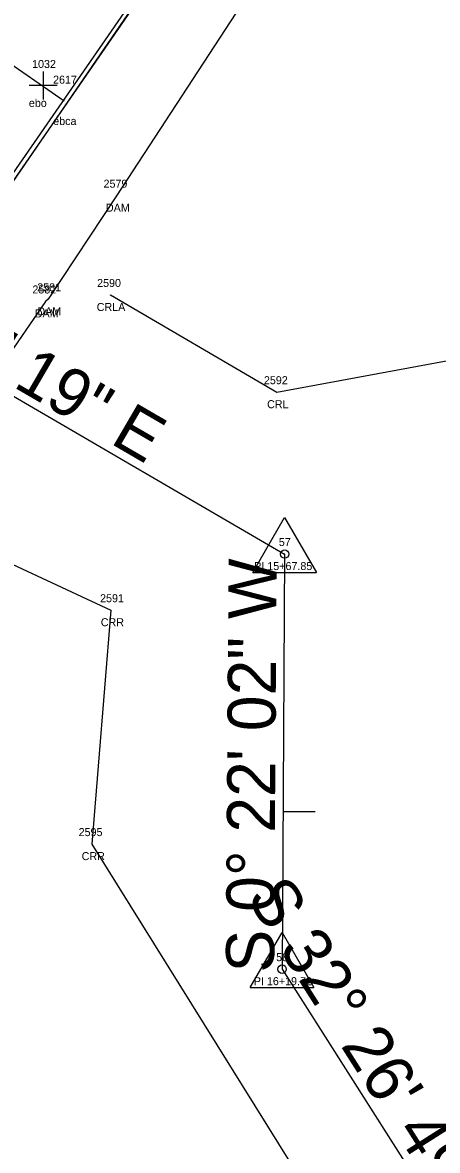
# Model space of a CAD drawing. Extents: x 2266664 to 2272542, y 716533 to 724777.
# Drawn here: x 2271122.9 to 2271174.6, y 722810 to 722951 of the extents above; entities that cross this region are included whole.
import ezdxf

# ---------------------------------------------------------------- set-up
doc = ezdxf.new("R2010")
doc.units = 0
for name, color, linetype in [('RD_EX_Bridge', 7, 'Continuous'), ('RD_EX_Dam', 7, 'Continuous'), ('RD_EX_Dam_txCode', 7, 'Continuous'), ('RD_EX_H2O', 7, 'Continuous'), ('RD_EX_H2O_txCode', 7, 'Continuous'), ('RD_EX_Misc', 7, 'Continuous'), ('RD_EX_Misc_txCode', 7, 'Continuous'), ('RD_HC_Cl', 7, 'Continuous'), ('RD_HC_Data', 7, 'Continuous'), ('RD_HC_Data_Tic', 7, 'Continuous'), ('RD_HC_txCode', 7, 'Continuous'), ('RD_SMD_Locator', 7, 'Continuous')]:
    doc.layers.add(name, color=color, linetype=linetype)

msp = doc.modelspace()

# ---------------------------------------------------------------- linework, layer by layer
at = {"layer": 'RD_EX_Bridge'}
msp.add_lwpolyline([(2271154.4, 722979.52), (2271126.52, 722998.67), (2271058.56, 722899.96), (2271086.24, 722880.86), (2271154.4, 722979.52)], dxfattribs=at)
at = {"layer": 'RD_EX_Dam'}
msp.add_lwpolyline([(2271152.21, 722956.41), (2271134.6, 722929.34), (2271126.04, 722916.39), (2271125.72, 722916.12), (2271108.94, 722891.69), (2271108.71, 722891.59), (2271102.6, 722882.8)], dxfattribs=at)
at = {"layer": 'RD_EX_H2O'}
for points in [[(2271133.84, 722916.93), (2271154.62, 722904.78), (2271177.12, 722908.95), (2271184.82, 722904.21), (2271203.34, 722891.87), (2271219.27, 722888.67), (2271223.62, 722883.63), (2271230.75, 722861.99), (2271243.25, 722836.75), (2271251.03, 722799.32), (2271257.08, 722776.2), (2271255.58, 722768.16), (2271246.13, 722767.9), (2271238.78, 722774.24), (2271234.51, 722782.33), (2271223.85, 722788.75), (2271179.02, 722817.03), (2271186.37, 722806.5), (2271219.28, 722770.37), (2271265.72, 722734.75), (2271320.84, 722716.15)], [(2271064.14, 722911.29), (2271095.29, 722888.89), (2271102.6, 722882.8), (2271117.86, 722885), (2271133.88, 722877.53), (2271131.49, 722848.3), (2271161.12, 722800.68), (2271158.38, 722790.92), (2271209.97, 722733.05), (2271257.97, 722699.07), (2271328.71, 722663.53), (2271328.76, 722676.23), (2271359.03, 722679.94), (2271405.02, 722657.62), (2271442.98, 722642.77), (2271440.33, 722616.88), (2271427.19, 722613.92), (2271489.22, 722575.87)]]:
    msp.add_lwpolyline(points, dxfattribs=at)
at = {"layer": 'RD_EX_Misc'}
for p, q in [((2271155.61, 722980.33), (2271085.82, 722879.3)), ((2271086.83, 722880.23), (2271154.05, 722978.35)), ((2271128.04, 722941.14), (2271100.17, 722960.49)), ((2271125.44, 722944.85), (2271125.44, 722941.35)), ((2271127.19, 722943.1), (2271123.69, 722943.1))]:
    msp.add_line(p, q, dxfattribs=at)
at = {"layer": 'RD_HC_Cl'}
for p, q in [((2271073.75, 722932.2), (2271155.58, 722884.55)), ((2271155.58, 722884.55), (2271155.25, 722832.67)), ((2271155.25, 722832.67), (2271173.74, 722803.59))]:
    msp.add_line(p, q, dxfattribs=at)
at = {"layer": 'RD_HC_Data'}
for p, q in [((2271151.61, 722882.25), (2271155.58, 722889.13)), ((2271155.58, 722889.13), (2271159.55, 722882.25)), ((2271151.61, 722882.25), (2271159.55, 722882.25)), ((2271151.28, 722830.38), (2271155.25, 722837.26)), ((2271155.25, 722837.26), (2271159.22, 722830.38)), ((2271151.28, 722830.38), (2271159.22, 722830.38))]:
    msp.add_line(p, q, dxfattribs=at)
for centre in [(2271155.58, 722884.55), (2271155.25, 722832.67)]:
    msp.add_circle(centre, 0.529, dxfattribs=at)
at = {"layer": 'RD_HC_Data_Tic'}
msp.add_line((2271155.38, 722852.39), (2271159.38, 722852.37), dxfattribs=at)
at = {"layer": 'RD_SMD_Locator'}
for centre in [(2271134.6, 722929.34), (2271125.72, 722916.12), (2271126.04, 722916.39), (2271133.84, 722916.93), (2271154.62, 722904.78), (2271155.58, 722884.55), (2271133.88, 722877.53), (2271131.49, 722848.3), (2271155.25, 722832.67)]:
    msp.add_circle(centre, 0.001, dxfattribs=at)

# ---------------------------------------------------------------- texts
at = {"layer": 'RD_EX_Dam_txCode'}
for s, p in [('2579', (2271132.97, 722930.34)), ('DAM', (2271133.27, 722927.34)), ('2582', (2271124.09, 722917.12)), ('2581', (2271124.69, 722917.39)), ('DAM', (2271124.39, 722914.12)), ('DAM', (2271124.71, 722914.39))]:
    msp.add_text(s, height=1, dxfattribs=at).set_placement(p)
at = {"layer": 'RD_EX_H2O_txCode'}
for s, p in [('2590', (2271132.17, 722917.93)), ('CRLA', (2271132.12, 722914.93)), ('2592', (2271152.99, 722905.78)), ('CRL', (2271153.39, 722902.78)), ('2591', (2271132.54, 722878.53)), ('CRR', (2271132.63, 722875.53)), ('2595', (2271129.86, 722849.3)), ('CRR', (2271130.24, 722846.3))]:
    msp.add_text(s, height=1, dxfattribs=at).set_placement(p)
at = {"layer": 'RD_EX_Misc_txCode'}
for s, p in [('1032', (2271124.05, 722945.3)), ('2617', (2271126.67, 722943.34)), ('ebo', (2271123.65, 722940.43)), ('ebca', (2271126.69, 722938.17))]:
    msp.add_text(s, height=1, dxfattribs=at).set_placement(p)
at = {"layer": 'RD_HC_Data'}
for s, rotation, p in [('S 59%%d 47\' 19" E', 329.7887, (2271091.63, 722922.94)), ('S 0%%d 22\' 02" W', 89.6327, (2271154.25, 722832.23)), ('S 32%%d 26\' 49" E', 302.4469, (2271150.72, 722841.66))]:
    msp.add_text(s, height=6, rotation=rotation, dxfattribs=at).set_placement(p)
at = {"layer": 'RD_HC_txCode'}
for s, p in [('57', (2271154.85, 722885.55)), ('PI 15+67.85', (2271151.78, 722882.55)), ('58', (2271154.52, 722833.67)), ('PI 16+19.72', (2271151.73, 722830.67))]:
    msp.add_text(s, height=1, dxfattribs=at).set_placement(p)

doc.saveas('drawing.dxf')
